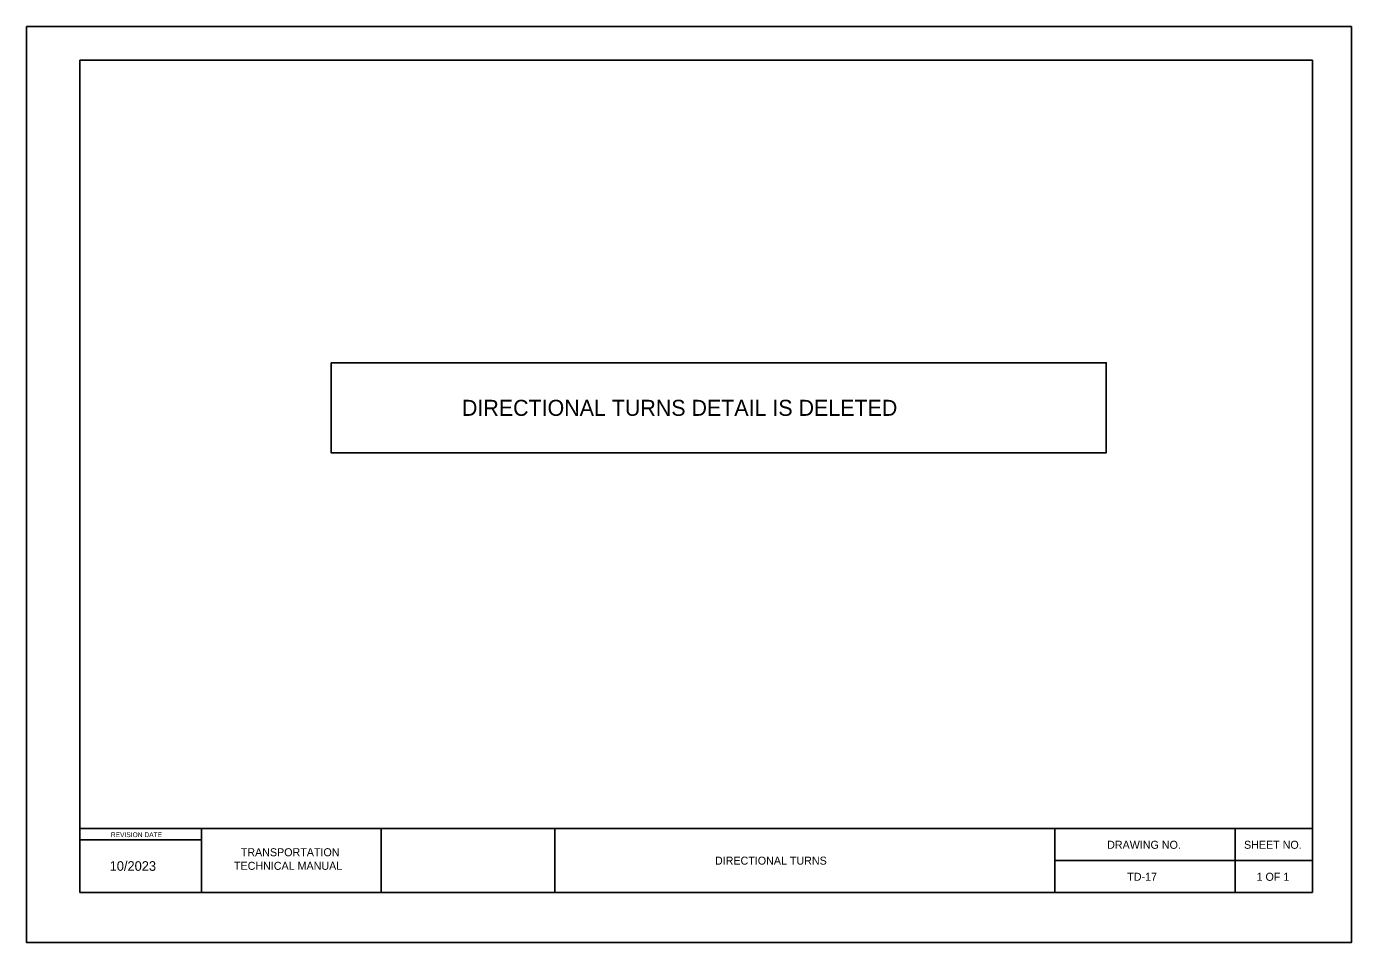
# Model space of a CAD drawing. Extents: x -14.6 to 39.7, y -12.4 to 25.1.
import ezdxf

# ---------------------------------------------------------------- set-up
doc = ezdxf.new("R2010")
doc.units = 0
for name, color, linetype in [('Default', 7, 'Continuous'), ('NonPlottingEle_dp', 7, 'Continuous'), ('SheetBorder_dp', 7, 'Continuous'), ('SheetLines_dp', 7, 'Continuous'), ('TextMinor', 7, 'Continuous')]:
    doc.layers.add(name, color=color, linetype=linetype)

msp = doc.modelspace()

# ---------------------------------------------------------------- linework, layer by layer
at = {"layer": 'Default'}
msp.add_lwpolyline([(-2.085, 11.359), (29.691, 11.359), (29.691, 7.669), (-2.085, 7.669)], close=True, dxfattribs=at)
at = {"layer": 'NonPlottingEle_dp'}
msp.add_lwpolyline([(38.12, 25.141), (-14.569, 25.141), (-14.569, -12.409), (39.74, -12.409), (39.74, 25.141)], close=True, dxfattribs=at)
at = {"layer": 'SheetBorder_dp'}
for p, q in [((-12.382, 23.76), (-12.382, -10.361)), ((-12.382, 23.76), (38.143, 23.76)), ((38.143, 23.76), (38.143, -10.361)), ((-12.382, -7.741), (38.143, -7.741)), ((-12.382, -10.361), (38.143, -10.361))]:
    msp.add_line(p, q, dxfattribs=at)
at = {"layer": 'SheetLines_dp'}
for p, q in [((-7.394, -7.736), (-7.394, -10.361)), ((-0.027, -7.736), (-0.027, -10.361)), ((7.087, -7.741), (7.087, -10.361)), ((27.582, -10.361), (27.582, -7.736)), ((34.972, -10.361), (34.972, -7.736)), ((-12.382, -8.196), (-7.394, -8.196)), ((27.582, -9.049), (38.143, -9.049))]:
    msp.add_line(p, q, dxfattribs=at)

# ---------------------------------------------------------------- texts
at = {"layer": 'TextMinor'}
for s, height, p in [('DIRECTIONAL TURNS DETAIL IS DELETED', 0.65617, (3.279, 9.181)), ('REVISION DATE', 0.19685, (-11.112, -8.089)), ('TRANSPORTATION', 0.32808, (-5.786, -8.873)), ('DRAWING NO.', 0.32808, (29.724, -8.567)), ('SHEET NO.', 0.3281, (35.335, -8.567)), ('10/2023', 0.3937, (-11.162, -9.47)), ('TECHNICAL MANUAL', 0.32808, (-6.066, -9.43)), ('DIRECTIONAL TURNS', 0.32808, (13.65, -9.217)), ('TD-17', 0.3281, (30.549, -9.879)), ('1 OF 1 ', 0.3281, (35.85, -9.879))]:
    msp.add_text(s, height=height, dxfattribs=at).set_placement(p)

doc.saveas('drawing.dxf')
